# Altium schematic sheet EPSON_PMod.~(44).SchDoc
size A4
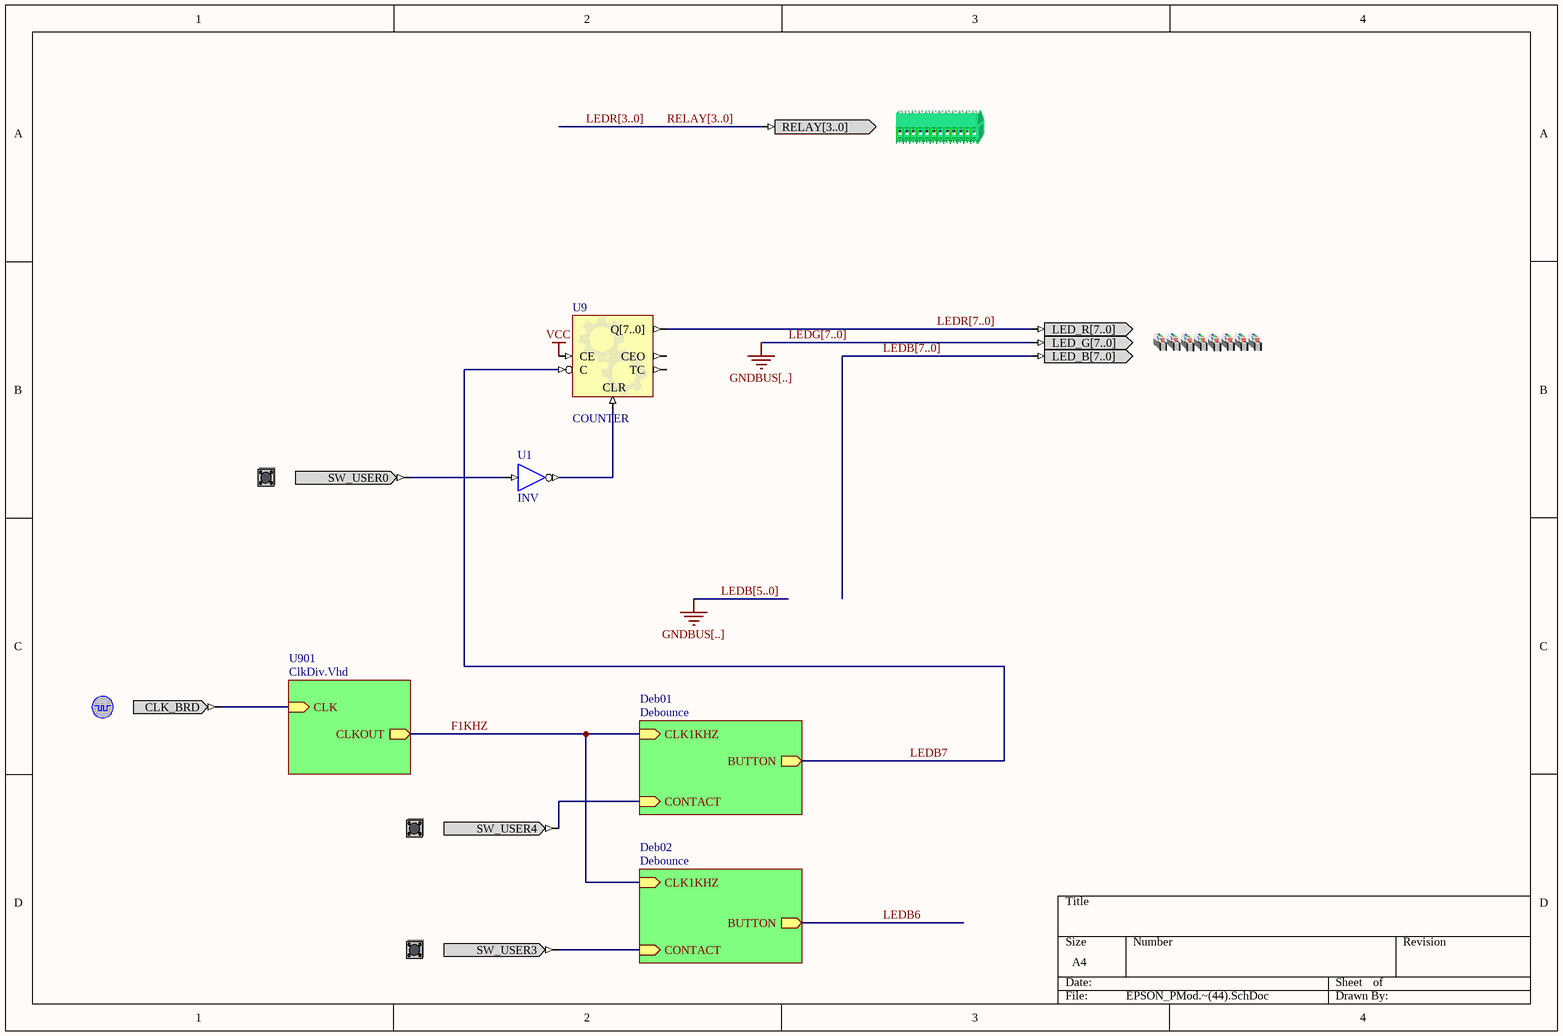
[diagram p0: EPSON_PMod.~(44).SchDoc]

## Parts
(Parts that share a designator on the sheet are numbered #1, #2 ... from top to bottom, then left to right.)
?#1  RELAYCNTR  (value not drawn)
?#2  LEDS_RGB  (value not drawn)
?#3  USER_BUTTON0  (value not drawn)
?#4  CLOCK_BOARD  (value not drawn)
?#5  USER_BUTTON4  (value not drawn)
?#6  USER_BUTTON3  (value not drawn)
U1  INV
U9  COUNTER

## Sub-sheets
Deb01 = Debounce: CONTACT (in), BUTTON (out), CLK1KHZ (in)
Deb02 = Debounce: CONTACT (in), BUTTON (out), CLK1KHZ (in)
U901 = ClkDiv.Vhd: CLK (in), CLKOUT (out)

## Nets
VCC: U9.CE
F1KHZ: sheet U901/CLKOUT, sheet Deb01/CLK1KHZ, sheet Deb02/CLK1KHZ
LEDB7: U9.C ; sheet Deb01/BUTTON
Net?#3_SW_USER0: ?#3.SW_USER0 U1.I
Net?#4_CLK_BRD: ?#4.CLK_BRD ; sheet U901/CLK
Net?#5_SW_USER4: ?#5.SW_USER4 ; sheet Deb01/CONTACT
Net?#6_SW_USER3: ?#6.SW_USER3 ; sheet Deb02/CONTACT
NetU1_O: U1.O U9.CLR

Not connected (* = marked no-connect by the designer): ?#1 RELAY[3..0]; ?#2 LED_B[7..0] LED_G[7..0] LED_R[7..0]; U9 CEO Q[7..0] TC

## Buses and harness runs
bus LEDB[5..0]
bus LEDB[7..0]
bus LEDG[7..0]
bus LEDR[3..0] = RELAY[3..0]
bus LEDR[7..0]

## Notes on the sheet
- Labels drawn without touching a wire or pin: GNDBUS[..]

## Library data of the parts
?#1 = RELAYCNTR: RELAY; PortComponent: True
?#2 = LEDS_RGB: LEDS RGB; PortComponent: True
?#3 = USER_BUTTON0: Generic User Button; PortComponent: True
?#4 = CLOCK_BOARD: Global System Clock Supply; PortComponent: True
?#5 = USER_BUTTON4: Generic User Button; PortComponent: True
?#6 = USER_BUTTON3: Generic User Button; PortComponent: True
U1 = INV: Inverter; FunctionalClass: Logic Primitive; ArchiveName: GENERIC; VHDLIB_SIM: GENERIC_LIB
U9 = COUNTER: Configurable Counter; ConfiguratorName: GENERIC_COUNTER; ConfigurationParameters: {}Version[1.0]{}Type[Binary]{}SyncReset[False]{}NegativeClockEdge[True]{}FixedDirection[True]{}IsIncrement[True]{}SignalWidth[8]{}MaxValue[255]{}BusOutput[True]{}Loadable[False]{}BusInput[False]{}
